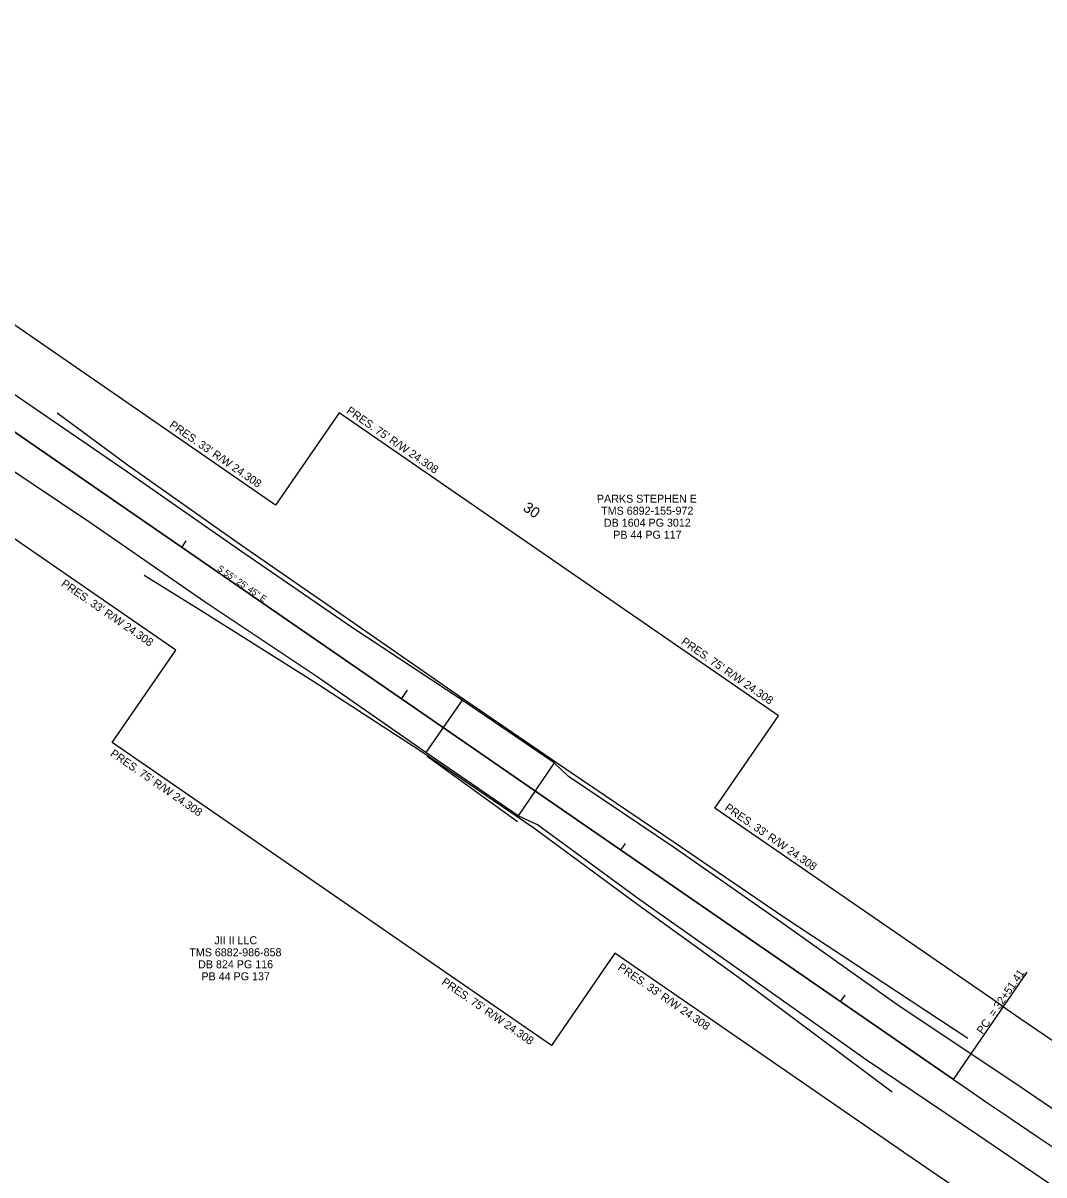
# Model space of a CAD drawing. Extents: x 1687085 to 1692731, y 826429 to 830660.
# Drawn here: x 1690388.3 to 1690771.1, y 829260.9 to 829692.6 of the extents above; entities that cross this region are included whole.
import ezdxf

# ---------------------------------------------------------------- set-up
doc = ezdxf.new("R2010")
doc.units = 0
for name, color, linetype in [('RD_EX_Bridge', 7, 'Continuous'), ('RD_EX_DV_TX_Prop', 7, 'Continuous'), ('RD_EX_GuardRail', 7, 'Continuous'), ('RD_EX_Road', 7, 'Continuous'), ('RD_EX_RW', 7, 'Continuous'), ('RD_EX_RW_TX', 7, 'Continuous'), ('RD_EX_SU_Telecom', 7, 'Continuous'), ('RD_HC_Cl', 7, 'Continuous'), ('RD_HC_Data', 7, 'Continuous'), ('RD_HC_Data_Tic', 7, 'Continuous'), ('RD_HC_TX_Sta20', 7, 'Continuous')]:
    doc.layers.add(name, color=color, linetype=linetype)

msp = doc.modelspace()

# ---------------------------------------------------------------- linework, layer by layer
at = {"layer": 'RD_EX_Bridge'}
for p, q in [((1690737.18, 829296.63), (1690201.95, 829665.46)), ((1690552.93, 829438.81), (1690539.33, 829419.15)), ((1690587.41, 829415.33), (1690573.96, 829395.49))]:
    msp.add_line(p, q, dxfattribs=at)
for points in [[(1690587.41, 829415.33), (1690552.93, 829438.81)], [(1690573.96, 829395.49), (1690539.33, 829419.15)]]:
    msp.add_lwpolyline(points, dxfattribs=at)
msp.add_arc((1693126.69, 832779.49), 4223.75, 235.54678, 242.14084, dxfattribs=at)
at = {"layer": 'RD_EX_GuardRail'}
for points in [[(1690742.56, 829312.02), (1690674.11, 829357.14), (1690632.47, 829385.5), (1690593.84, 829411.56), (1690551.93, 829440.17), (1690512.39, 829467.68), (1690468.63, 829497.92), (1690427.34, 829527.03), (1690401.05, 829546.38)], [(1690714.23, 829291.88), (1690657.92, 829333.84), (1690618.83, 829362.1), (1690579.79, 829390.8), (1690537.62, 829419.62), (1690496.99, 829445.92), (1690454.1, 829472.9), (1690433.7, 829485.47)]]:
    msp.add_lwpolyline(points, dxfattribs=at)
at = {"layer": 'RD_EX_Road'}
for points in [[(1691159.74, 829055.39), (1691114.69, 829079.17), (1691068.19, 829104.14), (1691024.6, 829128.48), (1690980.49, 829153.59), (1690936.85, 829180.48), (1690895.84, 829205.85), (1690850.04, 829234.88), (1690805.39, 829264.43), (1690760.12, 829295.25), (1690716.78, 829324.17), (1690673.22, 829355.13), (1690632.16, 829383.68), (1690592.78, 829410.17), (1690587.41, 829415.33), (1690552.93, 829438.81), (1690511.51, 829466.17), (1690467.43, 829496.42), (1690426.27, 829525.1), (1690383.68, 829554.25)], [(1691148.41, 829034.47), (1691102.99, 829058.12), (1691056.53, 829083.25), (1691012.35, 829108.03), (1690969.64, 829133.05), (1690924.56, 829160.07), (1690881.81, 829186.4), (1690837.69, 829214.92), (1690793.56, 829243.65), (1690746.18, 829275.86), (1690704.43, 829303.98), (1690659.8, 829335.6), (1690619.62, 829363.97), (1690581.14, 829392.07), (1690573.96, 829395.49), (1690539.33, 829419.15), (1690498.2, 829447.81), (1690456.6, 829475.49), (1690413.37, 829505.39), (1690370.29, 829534.15)]]:
    msp.add_lwpolyline(points, dxfattribs=at)
at = {"layer": 'RD_EX_RW'}
for p, q in [((1690483.01, 829511.86), (1690220.78, 829692.56)), ((1690506.84, 829546.44), (1690483.01, 829511.86)), ((1690671.53, 829432.96), (1690506.84, 829546.44)), ((1690421.73, 829422.93), (1690445.56, 829457.51)), ((1690647.69, 829398.37), (1690671.53, 829432.96)), ((1690755.87, 829323.83), (1690647.69, 829398.37)), ((1690610.24, 829344.03), (1690586.41, 829309.44))]:
    msp.add_line(p, q, dxfattribs=at)
for points in [[(1690445.56, 829457.51), (1690183.12, 829638.36), (1690183.01, 829638.44)], [(1690586.41, 829309.44), (1690421.73, 829422.93)], [(1690718.51, 829269.42), (1690718.48, 829269.44), (1690610.24, 829344.03)]]:
    msp.add_lwpolyline(points, dxfattribs=at)
for radius, start in [(4190.75, 235.54724), (4256.75, 235.54678)]:
    msp.add_arc((1693126.69, 832779.49), radius, start, 242.14084, dxfattribs=at)
at = {"layer": 'RD_EX_SU_Telecom'}
msp.add_lwpolyline([(1690573.74, 829393.23), (1690539.81, 829417.73)], dxfattribs=at)
at = {"layer": 'RD_HC_Cl'}
msp.add_line((1690201.95, 829665.46), (1690737.18, 829296.63), dxfattribs=at)
msp.add_arc((1693126.69, 832779.49), 4223.75, 235.54678, 242.14084, dxfattribs=at)
at = {"layer": 'RD_HC_Data'}
msp.add_line((1690737.18, 829296.63), (1690764.8, 829336.9), dxfattribs=at)
at = {"layer": 'RD_HC_Data_Tic'}
for p, q in [((1690447.82, 829496.03), (1690449.52, 829498.5)), ((1690530.16, 829439.29), (1690532.43, 829442.58)), ((1690612.5, 829382.55), (1690614.2, 829385.02)), ((1690694.84, 829325.81), (1690696.55, 829328.28))]:
    msp.add_line(p, q, dxfattribs=at)

# ---------------------------------------------------------------- texts
at = {"layer": 'RD_EX_DV_TX_Prop'}
for s, p in [('PARKS STEPHEN E', (1690603.49, 829512.78)), ('TMS 6892-155-972', (1690605.08, 829508.28)), ('DB 1604 PG 3012', (1690606.1, 829503.78)), ('PB 44 PG 117', (1690609.59, 829499.29)), ('JII II LLC', (1690460.03, 829347.31)), ('TMS 6882-986-858', (1690450.63, 829342.8)), ('DB 824 PG 116', (1690453.95, 829338.3)), ('PB 44 PG 137', (1690455.2, 829333.8))]:
    msp.add_text(s, height=3, rotation=0.0605, dxfattribs=at).set_placement(p)
at = {"layer": 'RD_EX_RW_TX'}
for s, p in [("PRES. 75' R/W 24.308", (1690509.26, 829546.6)), ("PRES. 33' R/W 24.308", (1690442.9, 829541.32)), ("PRES. 33' R/W 24.308", (1690402.35, 829481.82)), ("PRES. 75' R/W 24.308", (1690634.82, 829460.07)), ("PRES. 75' R/W 24.308", (1690420.73, 829418.15)), ("PRES. 33' R/W 24.308", (1690651.11, 829397.84)), ("PRES. 33' R/W 24.308", (1690611.05, 829338)), ("PRES. 75' R/W 24.308", (1690544.95, 829332.55))]:
    msp.add_text(s, height=3, rotation=325.4291, dxfattribs=at).set_placement(p)
at = {"layer": 'RD_HC_Data'}
for s, height, rotation, p in [('S 55%%d 25\' 45" E', 2.4, 325.4291, (1690460.87, 829487.64)), ('PC  = 32+51.41', 3, 55.5468, (1690748.08, 829313.41))]:
    msp.add_text(s, height=height, rotation=rotation, dxfattribs=at).set_placement(p)
at = {"layer": 'RD_HC_TX_Sta20'}
msp.add_text('30', height=4, rotation=325.4291, dxfattribs=at).set_placement((1690575.44, 829510.1))

doc.saveas('drawing.dxf')
